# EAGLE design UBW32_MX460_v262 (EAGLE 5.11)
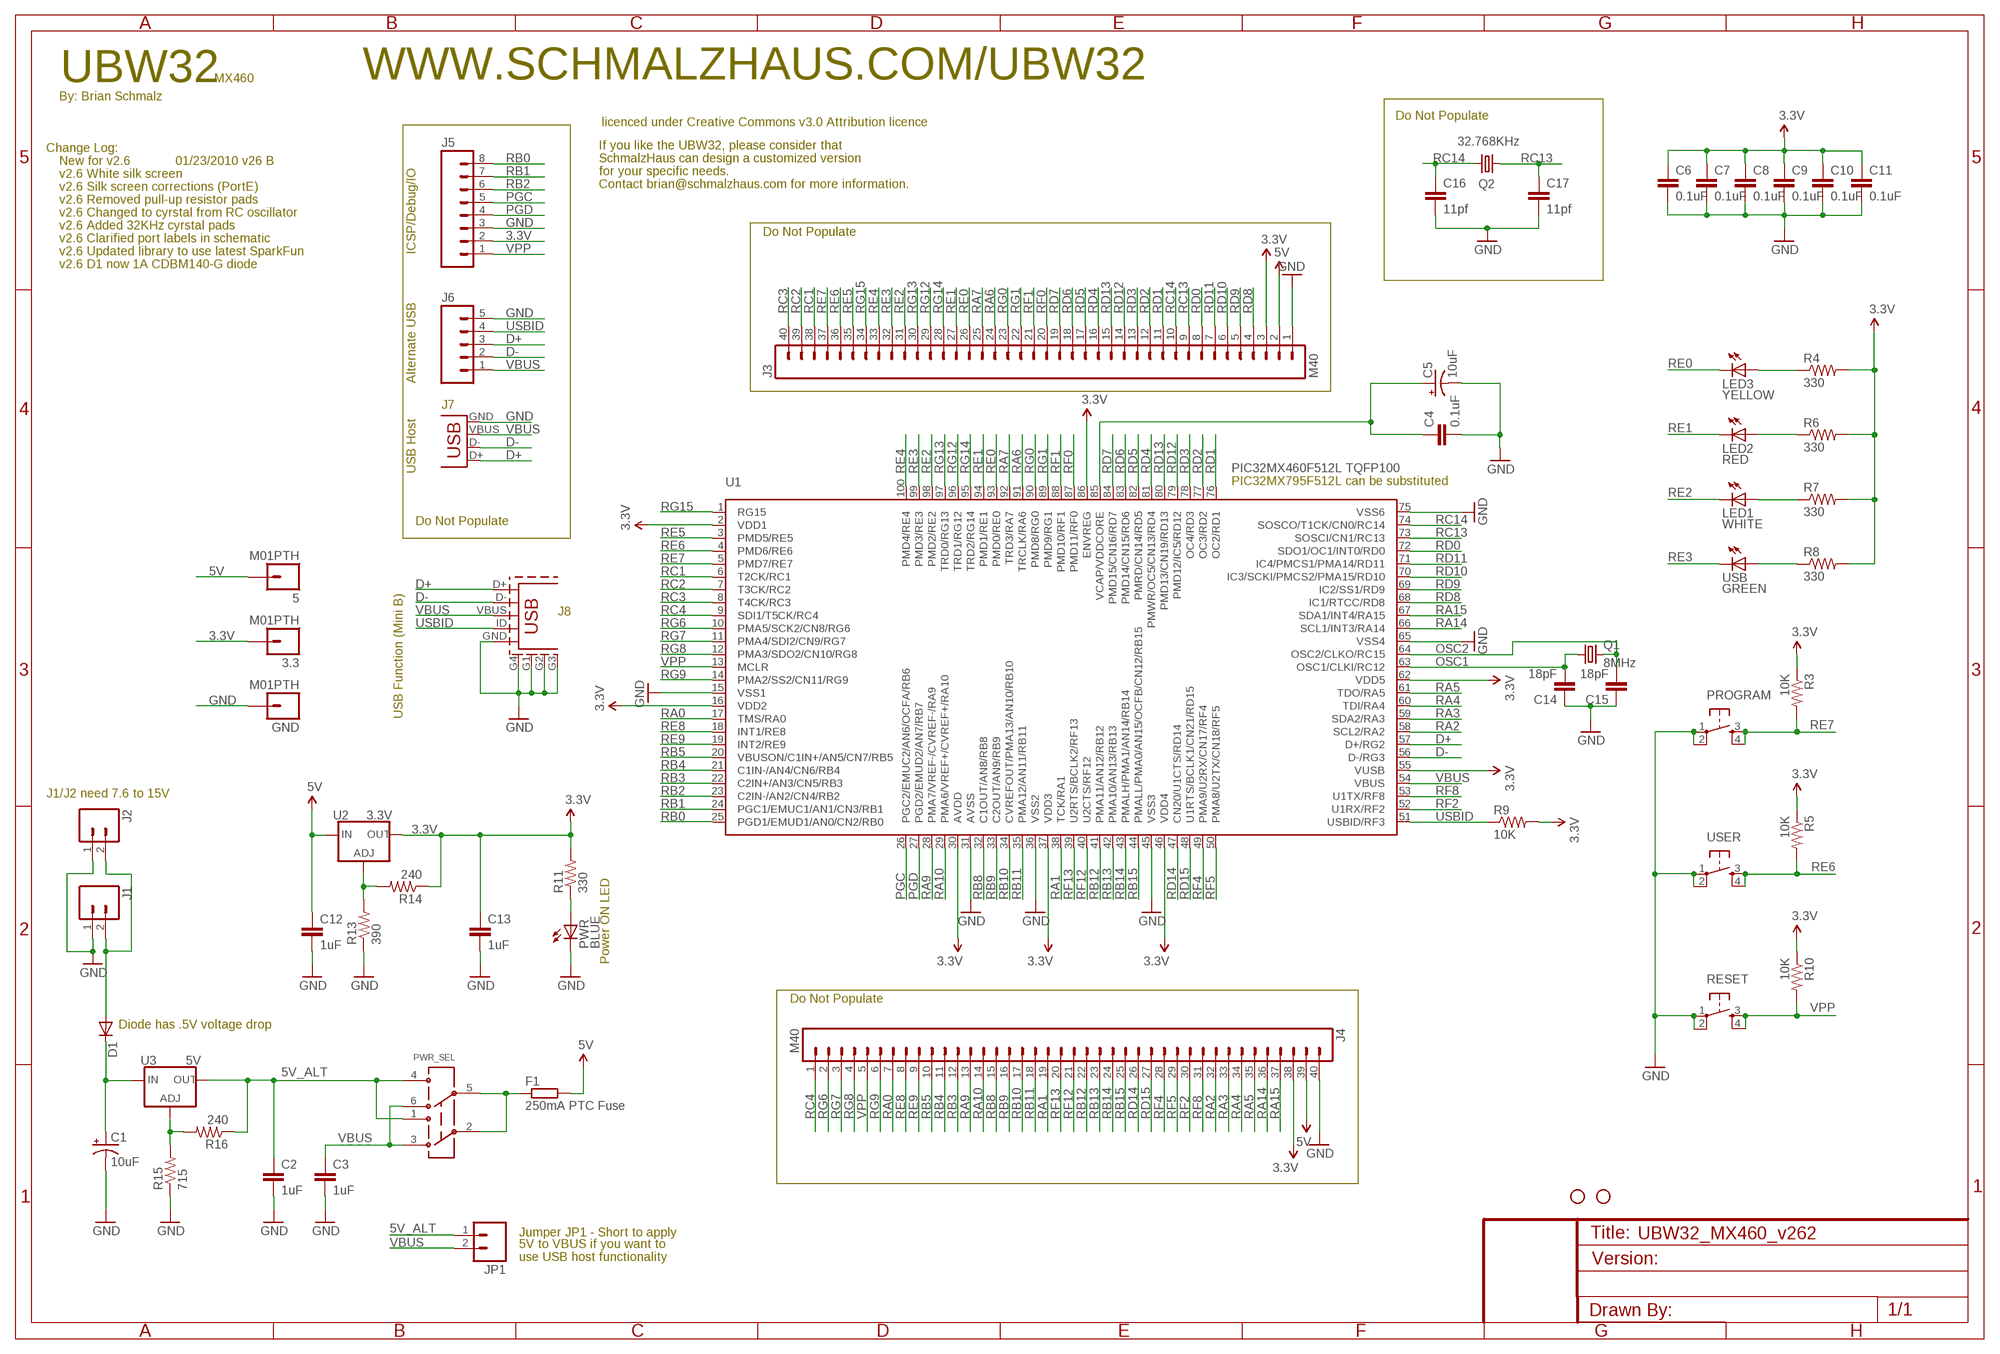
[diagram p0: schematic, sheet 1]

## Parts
3.3  M01PTH  [1X01]
5  M01PTH  [1X01]
C1  10uF  CAP_POL3528  [EIA3528]
C2  1uF  CAP0402-CAP  [0402-CAP]
C3  1uF  CAP0402-CAP  [0402-CAP]
C4  0.1uF  CAP0402-CAP  [0402-CAP]
C5  10uF  CAP_POL3528  [EIA3528]
C6  0.1uF  CAP0402-CAP  [0402-CAP]
C7  0.1uF  CAP0402-CAP  [0402-CAP]
C8  0.1uF  CAP0402-CAP  [0402-CAP]
C9  0.1uF  CAP0402-CAP  [0402-CAP]
C10  0.1uF  CAP0402  [C0402]
C11  0.1uF  CAP0402-CAP  [0402-CAP]
C12  1uF  CAP0402  [C0402]
C13  1uF  CAP0402  [C0402]
C14  18pF  CAP0402-CAP  [0402-CAP]
C15  18pF  CAP0402-CAP  [0402-CAP]
C16  11pf  CAP0402-CAP  [0402-CAP]
C17  11pf  CAP0402-CAP  [0402-CAP]
D1  DIODESMA  [SMA-DIODE]
F1  250mA PTC Fuse  R-EU_R1206  [R1206]
GND  M01PTH  [1X01]
J1  M02PTH  [1X02]
J2  M02-JST-2MM-SMT  [S2B-PH]
J3  M40  [1X40]
J4  M40  [1X40]
J5  M08  [1X08]
J6  M05PTH  [1X05]
J7  USB-A-S  [USB-A-S]
J8  USB_5PIN  [USB-MINIB]
JP1  M02PTH  [1X02]
LED1  WHITE  LED0603  [LED-0603]
LED2  RED  LED0603  [LED-0603]
LED3  YELLOW  LED0603  [LED-0603]
PROGRAM  TAC_SWITCHSND  [TACTILE_SWITCH_SMD]
PWR  BLUE  LED0603  [LED-0603]
PWR_SEL  AYZ0202  [AYZ0202]
Q1  8MHz  CRYSTAL5X3  [CRYSTAL-SMD-5X3]
Q2  32.768KHz  CRYSTAL32-SMD  [CRYSTAL-32KHZ-SMD]
R3  10K  RESISTOR0402-RES  [0402-RES]
R4  330  RESISTOR0402-RES  [0402-RES]
R5  10K  RESISTOR0402-RES  [0402-RES]
R6  330  RESISTOR0402-RES  [0402-RES]
R7  330  RESISTOR0402-RES  [0402-RES]
R8  330  RESISTOR0402-RES  [0402-RES]
R9  10K  RESISTOR0402-RES  [0402-RES]
R10  10K  RESISTOR0402-RES  [0402-RES]
R11  330  RESISTOR0402-RES  [0402-RES]
R13  390  RESISTOR0402-RES  [0402-RES]
R14  240  RESISTOR0402-RES  [0402-RES]
R15  715  RESISTOR0402-RES  [0402-RES]
R16  240  RESISTOR0402-RES  [0402-RES]
RESET  TAC_SWITCHSND  [TACTILE_SWITCH_SMD]
U1  PIC32MX460F512L TQFP100  PIC32MX4XXLTQFP100  [TQFP100]
U2  3.3V  V_REG_317SMD  [SOT223]
U3  5V  V_REG_317SMD  [SOT223]
U$6  STAND-OFF  [STAND-OFF]
U$7  STAND-OFF  [STAND-OFF]
USB  GREEN  LED0603  [LED-0603]
USER  TAC_SWITCHSND  [TACTILE_SWITCH_SMD]

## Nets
3.3V: 3.3.1 C6.1 C7.1 C8.1 C9.1 C10.1 C11.1 C13.1 J3.3 J4.38 J5.2 R3.1 R4.2 R5.1 R6.2 R7.2 R8.2 R9.2 R10.1 R11.2 R14.1 U1.2(VDD1) U1.16(VDD2) U1.30(AVDD) U1.37(VDD3) U1.46(VDD4) U1.55(VUSB) U1.62(VDD5) U1.86(ENVREG) U2.2(OUT)
5V: 5.1 C12.1 F1.2 J3.2 J4.39 U2.3(IN)
5V_ALT: C2.1 JP1.1 PWR_SEL.1 PWR_SEL.4 R16.1 U3.2(OUT)
D+: J6.3 J7.D+ J8.D+ U1.57(D+/RG2)
D-: J6.2 J7.D- J8.D- U1.56(D-/RG3)
GND: C1.C(-) C2.2 C3.2 C4.2 C5.C(-) C6.2 C7.2 C8.2 C9.2 C10.2 C11.2 C12.2 C13.2 C14.1 C15.1 C16.2 C17.2 GND.1 J1.1 J2.1 J3.1 J4.40 J5.3 J6.5 J7.GND J8.G1 J8.G2 J8.G3 J8.G4(SHIELD) J8.GND PROGRAM.1 PROGRAM.2 PWR.C R13.1 R15.1 RESET.1 RESET.2 U1.15(VSS1) U1.31(AVSS) U1.36(VSS2) U1.45(VSS3) U1.65(VSS4) U1.75(VSS6) USER.1 USER.2
N$1: D1.A J1.2 J2.2
N$2: F1.1 PWR_SEL.2 PWR_SEL.5
N$3: R13.2 R14.2 U2.1(ADJ)
N$4: R15.2 R16.2 U3.1(ADJ)
N$6: PWR.A R11.1
N$20: R8.1 USB.A
N$22: LED1.A R7.1
N$23: LED2.A R6.1
N$35: LED3.A R4.1
N$110: C4.1 C5.A(+) U1.85(VCAP/VDDCORE)
OSC1: C14.2 Q1.1 U1.63(OSC1/CLKI/RC12)
OSC2: C15.2 Q1.3 U1.64(OSC2/CLKO/RC15)
PGC: J5.5 U1.26(PGC2/EMUC2/AN6/OCFA/RB6)
PGD: J5.4 U1.27(PGD2/EMUD2/AN7/RB7)
RA0: J4.7 U1.17(TMS/RA0)
RA1: J4.19 U1.38(TCK/RA1)
RA2: J4.32 U1.58(SCL2/RA2)
RA3: J4.33 U1.59(SDA2/RA3)
RA4: J4.34 U1.60(TDI/RA4)
RA5: J4.35 U1.61(TDO/RA5)
RA6: J3.24 U1.91(TRCLK/RA6)
RA7: J3.25 U1.92(TRD3/RA7)
RA9: J4.13 U1.28(PMA7/VREF-/CVREF-/RA9)
RA10: J4.14 U1.29(PMA6/VREF+/CVREF+/RA10)
RA14: J4.36 U1.66(SCL1/INT3/RA14)
RA15: J4.37 U1.67(SDA1/INT4/RA15)
RB0: J5.8 U1.25(PGD1/EMUD1/AN0/CN2/RB0)
RB1: J5.7 U1.24(PGC1/EMUC1/AN1/CN3/RB1)
RB2: J5.6 U1.23(C2IN-/AN2/CN4/RB2)
RB3: J4.12 U1.22(C2IN+/AN3/CN5/RB3)
RB4: J4.11 U1.21(C1IN-/AN4/CN6/RB4)
RB5: J4.10 U1.20(VBUSON/C1IN+/AN5/CN7/RB5)
RB8: J4.15 U1.32(C1OUT/AN8/RB8)
RB9: J4.16 U1.33(C2OUT/AN9/RB9)
RB10: J4.17 U1.34(CVREFOUT/PMA13/AN10/RB10)
RB11: J4.18 U1.35(PMA12/AN11/RB11)
RB12: J4.22 U1.41(PMA11/AN12/RB12)
RB13: J4.23 U1.42(PMA10/AN13/RB13)
RB14: J4.24 U1.43(PMALH/PMA1/AN14/RB14)
RB15: J4.25 U1.44(PMALL/PMA0/AN15/OCFB/CN12/RB15)
RC1: J3.38 U1.6(T2CK/RC1)
RC2: J3.39 U1.7(T3CK/RC2)
RC3: J3.40 U1.8(T4CK/RC3)
RC4: J4.1 U1.9(SDI1/T5CK/RC4)
RC13: C17.1 J3.9 Q2.X1 U1.73(SOSCI/CN1/RC13)
RC14: C16.1 J3.10 Q2.X2 U1.74(SOSCO/T1CK/CN0/RC14)
RD0: J3.8 U1.72(SDO1/OC1/INT0/RD0)
RD1: J3.11 U1.76(OC2/RD1)
RD2: J3.12 U1.77(OC3/RD2)
RD3: J3.13 U1.78(OC4/RD3)
RD4: J3.16 U1.81(PMWR/OC5/CN13/RD4)
RD5: J3.17 U1.82(PMRD/CN14/RD5)
RD6: J3.18 U1.83(PMD14/CN15/RD6)
RD7: J3.19 U1.84(PMD15/CN16/RD7)
RD8: J3.4 U1.68(IC1/RTCC/RD8)
RD9: J3.5 U1.69(IC2/SS1/RD9)
RD10: J3.6 U1.70(IC3/SCKI/PMCS2/PMA15/RD10)
RD11: J3.7 U1.71(IC4/PMCS1/PMA14/RD11)
RD12: J3.14 U1.79(PMD12/IC5/RD12)
RD13: J3.15 U1.80(PMD13/CN19/RD13)
RD14: J4.26 U1.47(CN20/U1CTS/RD14)
RD15: J4.27 U1.48(U1RTS/BCLK1/CN21/RD15)
RE0: J3.26 LED3.C U1.93(PMD0/RE0)
RE1: J3.27 LED2.C U1.94(PMD1/RE1)
RE2: J3.31 LED1.C U1.98(PMD2/RE2)
RE3: J3.32 U1.99(PMD3/RE3) USB.C
RE4: J3.33 U1.100(PMD4/RE4)
RE5: J3.35 U1.3(PMD5/RE5)
RE6: J3.36 R5.2 U1.4(PMD6/RE6) USER.3 USER.4
RE7: J3.37 PROGRAM.3 PROGRAM.4 R3.2 U1.5(PMD7/RE7)
RE8: J4.8 U1.18(INT1/RE8)
RE9: J4.9 U1.19(INT2/RE9)
RF0: J3.20 U1.87(PMD11/RF0)
RF1: J3.21 U1.88(PMD10/RF1)
RF2: J4.30 U1.52(U1RX/RF2)
RF4: J4.28 U1.49(PMA9/U2RX/CN17/RF4)
RF5: J4.29 U1.50(PMA8/U2TX/CN18/RF5)
RF8: J4.31 U1.53(U1TX/RF8)
RF12: J4.21 U1.40(U2CTS/RF12)
RF13: J4.20 U1.39(U2RTS/BCLK2/RF13)
RG0: J3.23 U1.90(PMD8/RG0)
RG1: J3.22 U1.89(PMD9/RG1)
RG6: J4.2 U1.10(PMA5/SCK2/CN8/RG6)
RG7: J4.3 U1.11(PMA4/SDI2/CN9/RG7)
RG8: J4.4 U1.12(PMA3/SDO2/CN10/RG8)
RG9: J4.6 U1.14(PMA2/SS2/CN11/RG9)
RG12: J3.29 U1.96(TRD1/RG12)
RG13: J3.30 U1.97(TRD0/RG13)
RG14: J3.28 U1.95(TRD2/RG14)
RG15: J3.34 U1.1(RG15)
USBID: J6.4 J8.ID(USB_ID) R9.1 U1.51(USBID/RF3)
VBUS: C3.1 J6.1 J7.VBUS J8.VBUS JP1.2 PWR_SEL.3 PWR_SEL.6 U1.54(VBUS)
VIN_RAW: C1.A(+) D1.C U3.3(IN)
VPP: J4.5 J5.1 R10.2 RESET.3 RESET.4 U1.13(MCLR)

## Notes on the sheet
- UBW32 | MX460 | WWW.SCHMALZHAUS.COM/UBW32
- By: Brian Schmalz
- Do Not Populate
- licenced under Creative Commons v3.0 Attribution licence
- Change Log: | If you like the UBW32, please consider that
- New for v2.6 | 01/23/2010 v26 B | SchmalzHaus can design a customized version
- v2.6 White silk screen | for your specific needs.
- v2.6 Silk screen corrections (PortE) | Contact brian@schmalzhaus.com for more information.
- v2.6 Removed pull-up resistor pads
- v2.6 Changed to cyrstal from RC oscillator
- v2.6 Added 32KHz cyrstal pads
- Do Not Populate
- v2.6 Clarified port labels in schematic
- v2.6 Updated library to use latest SparkFun | ICSP/Debug/IO
- v2.6 D1 now 1A CDBM140-G diode
- Alternate USB
- J7
- USB Host
- PIC32MX795F512L can be substituted
- Do Not Populate
- J8
- USB Function (Mini B)
- J1/J2 need 7.6 to 15V
- Power ON LED
- Do Not Populate
- Diode has .5V voltage drop
- Jumper JP1 - Short to apply
- 5V to VBUS if you want to
- use USB host functionality

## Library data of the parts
3.3 5 GND = SparkFun-12-01-09:M01: Header 1
C1 C5 = SparkFun02-20-08:CAP_POL: Capacitor Polarized
C2-C4 C6-C9 C11 C14-C17 = SparkFun:CAP: Capacitor
C10 C12 C13 = SparkFun02-20-08:CAP: Capacitor
D1 = SparkFun-12-01-09:DIODE: Diode
F1 = resistor:R-EU_: RESISTOR, European symbol
J1 JP1 = SparkFun-12-01-09:M02: Header 2
J2 = SparkFun:M02: Header 2
J3 J4 = SchmalzHaus:M40
J5 = SchmalzHaus:M08: Header 8 Standard 8-pin 0.1" header. Use with straight break away headers (SKU : PRT-00116), right angle break away headers (PRT-00553), swiss pins (PRT-00743), machine pins (PRT-00117), and female headers (PRT-00115).
J6 = SparkFun-12-01-09:M05: Header 5 Standard 5-pin 0.1" header. Use with straight break away headers (SKU : PRT-00116), right angle break away headers (PRT-00553), swiss pins (PRT-00743), machine pins (PRT-00117), and female headers (PRT-00115). Molex polarized connector foot print use with SKU : PRT-08230 with associated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
J7 = SparkFun02-20-08:USB: USB Connectors USB-B-PTH is fully proven SKU : PRT-00139 USB-miniB is fully proven SKU : PRT-00587 USB-A-PCB is untested. USB-A-H is throughly reviewed, but untested. Spark Fun Electronics SKU : PRT-00437 USB-B-SMT is throughly reviewed, but untested. Needs silkscreen touching up. USB-A-S has not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
J8 = SparkFun02-20-08:USB_5PIN
LED1-LED3 PWR USB = SparkFun:LED: LEDs
PROGRAM RESET USER = SparkFun02-20-08:TAC_SWITCH: Momentary Switch Button commonly used for reset or general input. Spark Fun Electronics SKU : COM-00097
PWR_SEL = SparkFun02-20-08:AYZ0202: SPDT Slide Switch Simple SMD single-pull double-throw slide switch. Good for less than 350mA power switch, switching UARTs between devices, etc. Spark Fun Electronics SKU : COM-00597
Q1 = SparkFun11_03_09:CRYSTAL: Crystals
Q2 = SchmalzHaus:CRYSTAL: Crystals
R3-R11 R13-R16 = SparkFun:RESISTOR: Resistor
U1 = SchmalzHaus:PIC32MX4XXL
U2 U3 = SparkFun:V_REG_317: Voltage Regulator Standard LM317 adjustable voltage regulator. AOI (Adjust Output Input). Google 'LM317 Calculator' for easy to use app to get the two resistor values needed. 240/720 for 5V output. 240/390 for 3.3V output. Spark Fun Electronics SKU : COM-00527
U$6 U$7 = SparkFun02-20-08:STAND-OFF: Stand Off

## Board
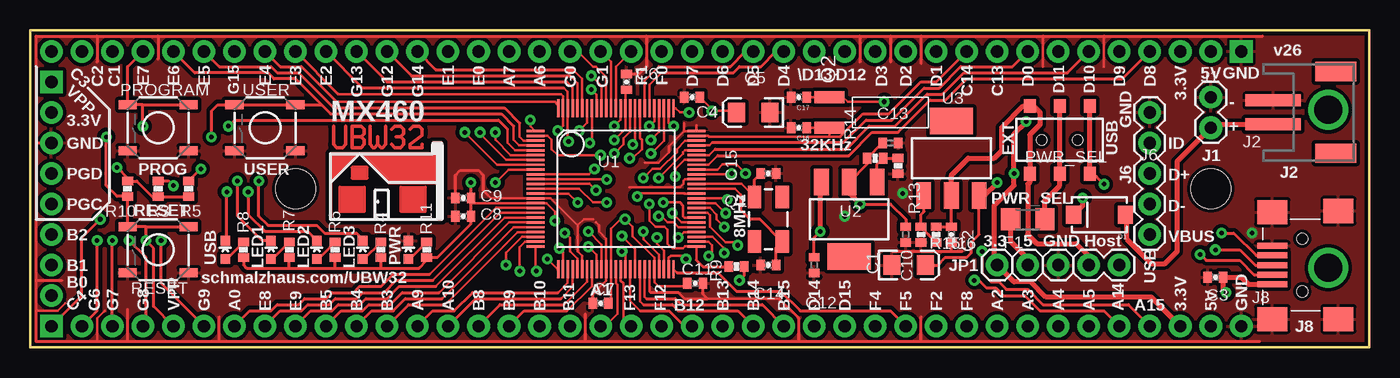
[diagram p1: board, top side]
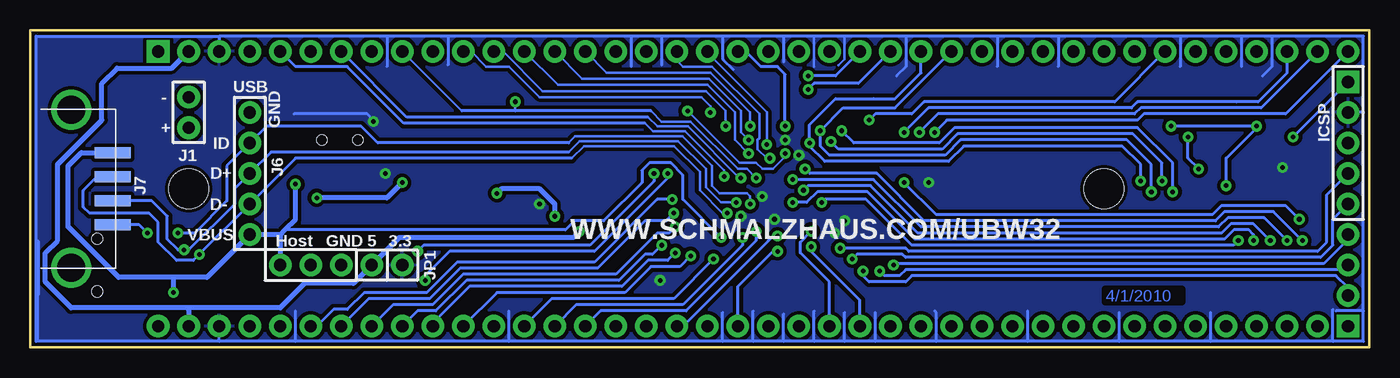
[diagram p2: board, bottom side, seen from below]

Size 111.51 x 26.42 mm. Coordinates in mm from the lower left corner, seen from the top.
Outline: 0,26.42 111.51,26.42 111.51,0 0,0 0,26.42
Copper layers (1*16): Top 0.035mm / dielectric 1.5mm / Bottom 0.035mm
Design rules "SparkFun *": minimum track width 8mil, minimum drill 15mil, track to track 8mil, track to pad 8mil, pad to pad 8mil, via to via 8mil, smd to smd 8mil, copper to edge 8mil, drill to drill 8mil, minimum pad ring 12mil, minimum via ring 10mil, stop-mask expansion 4mil, vias tented up to drill 20mil, thermal gap 10mil

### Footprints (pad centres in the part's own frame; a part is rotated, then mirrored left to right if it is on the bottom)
1X01 = drill 1.016 pad 1.88 round: 1 0,0
EIA3216 = smd 1.4 x 1.6: A 1.4,0; C -1.4,0
0402-CAP = smd 0.7 x 0.9: 1 -0.65,0; 2 0.65,0
C0402 = smd 0.7 x 0.9: 1 -0.65,0; 2 0.65,0
SMA-DIODE = smd 1.27 x 1.47: A -2.15,0; C 2.15,0
R1206 = smd 1.6 x 1.803: 1 -1.422,0; 2 1.422,0
1X02 = drill 1.016 pad 1.88 round: 1 0,0; 2 2.54,0
S2B-PH = smd 1 x 4.6: 1 -1,-3.7; 2 1,-3.7 | smd 1.6 x 3.4: NC1 -3.4,1.5; NC2 3.4,1.5
1X40 = drill 1.016 pad 1.88 square: 1 -49.53,0 | drill 1.016 pad 1.88 round: 2 -46.99,0; 3 -44.45,0; 4 -41.91,0; 5 -39.37,0; 6 -36.83,0; 7 -34.29,0; 8 -31.75,0; 9 -29.21,0; 10 -26.67,0; 11 -24.13,0; 12 -21.59,0; 13 -19.05,0; 14 -16.51,0; 15 -13.97,0; 16 -11.43,0; 17 -8.89,0; 18 -6.35,0; 19 -3.81,0; 20 -1.27,0; 21 1.27,0; 22 3.81,0; 23 6.35,0; 24 8.89,0; 25 11.43,0; 26 13.97,0; 27 16.51,0; 28 19.05,0; 29 21.59,0; 30 24.13,0; 31 26.67,0; 32 29.21,0; 33 31.75,0; 34 34.29,0; 35 36.83,0; 36 39.37,0; 37 41.91,0; 38 44.45,0; 39 46.99,0; 40 49.53,0
1X08 = drill 1.016 pad 1.88 square: 1 0,0 | drill 1.016 pad 1.88 round: 2 2.54,0; 3 5.08,0; 4 7.62,0; 5 10.16,0; 6 12.7,0; 7 15.24,0; 8 17.78,0
1X05 = drill 1.016 pad 1.88 round: 1 0,0; 2 2.54,0; 3 5.08,0; 4 7.62,0; 5 10.16,0
USB-A-S = smd 3 x 0.9: D+ 3.45,-1; D- 3.45,1; GND 3.45,-3; VBUS 3.45,3 | drill 2.311 round: P$5 0,-6.566; P$6 0,6.566
USB-MINIB = smd 2.5 x 0.5: D+ 2.5,0; D- 2.5,0.8; GND 2.5,-1.6; ID 2.5,-0.8; VBUS 2.5,1.6 | smd 2.5 x 2: G1 -3,4.5; G2 2.5,4.5; G3 -3,-4.5; G4 2.5,-4.4 | hole 0.9: 0,2.2; 0,-2.2
LED-0603 = smd 0.8 x 0.8: A 0,-0.75; C 0,0.75
TACTILE_SWITCH_SMD = smd 1.524 x 0.762: 1 -2.54,1.905; 2 2.54,1.905; 3 -2.54,-1.905; 4 2.54,-1.905
AYZ0202 = smd 1 x 1.15: 1 -2.5,2.825; 2 0,2.825; 3 2.5,2.825; 4 -2.5,-2.825; 5 0,-2.825; 6 2.5,-2.825 | hole 0.85: 1.5,0; -1.5,0
CRYSTAL-SMD-5X3 = smd 1.9 x 1.1: 1 -1.85,-1.15; 2 1.85,-1.15; 3 1.85,1.15; 4 -1.85,1.15
CRYSTAL-32KHZ-SMD = smd 1 x 2.5: X1 -1.27,0; X2 1.27,0
0402-RES = smd 0.7 x 0.9: 1 -0.65,0; 2 0.65,0
TQFP100 = smd 0.2 x 1.5: 1 -4.8,-6.7; 2 -4.4,-6.7; 3 -4,-6.7; 4 -3.6,-6.7; 5 -3.2,-6.7; 6 -2.8,-6.7; 7 -2.4,-6.7; 8 -2,-6.7; 9 -1.6,-6.7; 10 -1.2,-6.7; 11 -0.8,-6.7; 12 -0.4,-6.7; 13 0,-6.7; 14 0.4,-6.7; 15 0.8,-6.7; 16 1.2,-6.7; 17 1.6,-6.7; 18 2,-6.7; 19 2.4,-6.7; 20 2.8,-6.7; 21 3.2,-6.7; 22 3.6,-6.7; 23 4,-6.7; 24 4.4,-6.7; 25 4.8,-6.7; 51 4.8,6.7; 52 4.4,6.7; 53 4,6.7; 54 3.6,6.7; 55 3.2,6.7; 56 2.8,6.7; 57 2.4,6.7; 58 2,6.7; 59 1.6,6.7; 60 1.2,6.7; 61 0.8,6.7; 62 0.4,6.7; 63 0,6.7; 64 -0.4,6.7; 65 -0.8,6.7; 66 -1.2,6.7; 67 -1.6,6.7; 68 -2,6.7; 69 -2.4,6.7; 70 -2.8,6.7; 71 -3.2,6.7; 72 -3.6,6.7; 73 -4,6.7; 74 -4.4,6.7; 75 -4.8,6.7 | smd 1.5 x 0.2: 26 6.7,-4.8; 27 6.7,-4.4; 28 6.7,-4; 29 6.7,-3.6; 30 6.7,-3.2; 31 6.7,-2.8; 32 6.7,-2.4; 33 6.7,-2; 34 6.7,-1.6; 35 6.7,-1.2; 36 6.7,-0.8; 37 6.7,-0.4; 38 6.7,0; 39 6.7,0.4; 40 6.7,0.8; 41 6.7,1.2; 42 6.7,1.6; 43 6.7,2; 44 6.7,2.4; 45 6.7,2.8; 46 6.7,3.2; 47 6.7,3.6; 48 6.7,4; 49 6.7,4.4; 50 6.7,4.8; 76 -6.7,4.8; 77 -6.7,4.4; 78 -6.7,4; 79 -6.7,3.6; 80 -6.7,3.2; 81 -6.7,2.8; 82 -6.7,2.4; 83 -6.7,2; 84 -6.7,1.6; 85 -6.7,1.2; 86 -6.7,0.8; 87 -6.7,0.4; 88 -6.7,0; 89 -6.7,-0.4; 90 -6.7,-0.8; 91 -6.7,-1.2; 92 -6.7,-1.6; 93 -6.7,-2; 94 -6.7,-2.4; 95 -6.7,-2.8; 96 -6.7,-3.2; 97 -6.7,-3.6; 98 -6.7,-4; 99 -6.7,-4.4; 100 -6.7,-4.8
SOT223 = smd 1.219 x 2.235: 1 -2.311,-3.099; 2 0,-3.099; 3 2.311,-3.099 | smd 3.6 x 2.2: 4 0,3.099
STAND-OFF = hole 3.302: 0,0

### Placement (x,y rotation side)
3.3  80.52,6.86 0 top
5  83.06,6.86 0 top
C1  10uF  [EIA3216]  73.15,6.86 0 top
C2  76.71,9.4 270 top
C3  98.68,5.84 180 top
C4  55.12,20.83 180 top
C5  10uF  [EIA3216]  60.2,19.56 180 top
C6  49.66,22.1 90 top
C7  47.5,3.68 180 top
C8  36.07,10.92 180 top
C9  36.07,12.45 180 top
C10  72.9,9.4 270 top
C11  55.37,5.33 0 top
C12  65.28,6.86 270 top
C13  71.63,17.02 0 top
C14  61.47,6.86 0 top
C15  61.47,14.48 180 top
C16  64.01,18.29 180 top
C17  64.01,20.83 180 top
D1  89.03,11.05 180 top
F1  83.06,10.67 180 top
GND  85.6,6.86 0 top
J1  98.3,20.83 270 top
J2  107.19,19.56 270 top
J3  51.31,24.64 180 top
J4  51.31,1.78 0 top
J5  1.78,22.1 270 top
J6  93.22,9.4 90 top
J7  108.08,13.21 0 bottom
J8  105.92,6.86 180 top
JP1  88.14,6.86 0 top
LED1  20.07,8.13 0 top
LED2  23.88,8.13 0 top
LED3  27.69,8.13 0 top
PROGRAM  10.67,18.29 180 top
PWR  31.5,8.13 0 top
PWR_SEL  85.72,17.27 0 top
Q1  61.47,10.67 90 top
Q2  66.55,19.56 270 top
R3  10.67,13.21 90 top
R4  29.21,8.13 270 top
R5  13.21,13.21 90 top
R6  25.4,8.13 270 top
R7  21.59,8.13 270 top
R8  17.78,8.13 270 top
R9  58.8,6.73 0 top
R10  8.13,13.21 270 top
R11  33.02,8.13 270 top
R13  72.26,15.11 90 top
R14  70.36,15.75 0 top
R15  74.17,9.4 90 top
R16  75.44,9.4 270 top
RESET  10.67,8.13 180 top
U1  48.77,13.21 270 top
U2  68.2,10.67 180 top
U3  76.71,15.75 0 top
U$3  [UBW32]  29.59,17.91 0 top
U$5  [SCHMALZHAUS]  28.83,13.21 0 top
U$6  98.3,13.21 0 top
U$7  22.1,13.21 0 top
USB  16.26,8.13 0 top
USER  19.56,18.29 180 top

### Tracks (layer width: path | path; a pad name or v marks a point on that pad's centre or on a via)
3.3V  (via drill 0.38)
  Top 0.203: v48.64,17.27 49.57,18.2 U1.86 49.57,21.36 arc-90 C6.1 | v43.69,10.54 43.69,11.3 42.98,12.01 U1.16 36.77,12.01 | v44.51,9.52 44.58,9.52 44.96,9.14 44.96,8 45.57,7.39 U1.30 | U1.2 43.1,17.61 43.43,17.27 43.43,16.51 43.94,16 v47.5,16 | 48.37,3.92 U1.37 48.37,9.89 49.15,10.67 v49.53,10.67 50.16,10.03 50.16,9.27 51.97,7.47 U1.46 51.97,5.44 52.32,5.08 54.48,5.08 54.74,5.33 C11.1 | U1.62 54.5,12.81 54.48,12.83 50.8,12.83 v50.55,12.57 | U1.55 54,10.01 53.59,10.41 53.09,10.41 52.58,10.92 v52.32,10.92
  Top 0.254: v36.7,13.72 36.72,13.7 C9.1 36.7,12.45 36.7,11.94 | 36.7,10.92 C8.1 | 36.7,10.92 36.7,11.94 | 36.7,11.94 36.77,12.01 | 36.7,10.92 36.7,10.29 33.91,7.49 33.02,7.49 R11.2 33.02,7.24 32.38,6.6 29.21,6.6 | 21.59,6.6 25.4,6.6 | 25.4,6.6 29.21,6.6 | 29.21,6.6 R4.2 | 25.4,6.6 R6.2 | 21.59,6.6 R7.2 | R8.2 17.78,6.87 18.05,6.6 21.59,6.6 | C7.1 48.13,3.68 48.37,3.92 | R5.1 R3.1 10.18,12.56 8.89,13.84 8.14,13.84 R10.1 8.13,14.1 v7.24,14.99 | C13.1 R14.1 69.71,15.28 U2.2 | 72.88,10.03 C10.1 72.9,10.67 71.63,11.94 v69.09,11.94 | R9.2 59.45,5.98 v59.05,5.59
  Top 0.406: J4.38 93.34,4.19 84.58,4.19 83.31,5.46 81.91,5.46 3.3.1 80.26,7.11 80.26,11.81 81.91,13.46 v81.91,14.48 81.91,17.78 v82.93,18.8 | v69.09,11.94 68.2,12.83 U2.2
  Bottom 0.203: 43.69,25.91 43.69,24 44.2,23.49 | 46.23,25.91 46.23,23.37
  Bottom 0.254: 89.53,19.43 83.44,19.43 82.93,18.92 v82.93,18.8 | 0.51,3.05 0.51,0.51 3.05,0.51 | 0.51,3.05 0.51,19.56 | 0.51,19.56 0.51,25.91 8.13,25.91 | 8.13,25.91 10.67,25.91 | 10.67,25.91 15.75,25.91 | 15.75,25.91 25.91,25.91 | 25.91,25.91 30.99,25.91 | 30.99,25.91 38.61,25.91 | 38.61,25.91 43.69,25.91 46.23,25.91 48.77,25.91 | 48.77,25.91 53.85,25.91 | 81.79,25.91 95.76,25.91 | 76.71,25.91 81.79,25.91 | 61.47,25.91 76.71,25.91 | 58.93,25.91 61.47,25.91 | 53.85,25.91 58.93,25.91 | 95.76,25.91 111,25.91 111,0.51 | 3.05,0.51 13.21,0.51 | 13.21,0.51 20.83,0.51 | 20.83,0.51 28.45,0.51 | 28.45,0.51 36.07,0.51 | 36.07,0.51 41.15,0.51 | 41.15,0.51 43.69,0.51 | 43.69,0.51 46.23,0.51 | 46.23,0.51 48.77,0.51 | 48.77,0.51 51.31,0.51 | 51.31,0.51 53.85,0.51 | 53.85,0.51 71.63,0.51 | 71.63,0.51 89.41,0.51 | 89.41,0.51 95.76,0.51 | 95.76,0.51 111,0.51 | 0.51,19.56 2.03,19.56 | 0.51,3.05 2.79,3.05 | 3.05,0.51 3.05,3.17 | 41.15,0.51 41.15,2.92 | 48.77,0.51 48.77,2.79 | 53.85,25.91 53.85,24 52.96,23.11 | 95.76,25.91 95.76,24.13 | 95.76,0.51 J4.38 | 89.41,0.51 89.41,3.05 | 25.91,25.91 25.91,23.37 | 30.99,25.91 30.99,23.37 | 48.77,25.91 48.77,23.75 | 38.61,25.91 38.61,23.37 39.37,22.61 | 15.75,25.91 15.75,23.37 | 10.67,25.91 10.67,23.37 | 8.13,25.91 8.13,23.37 8.89,22.61 | 13.21,0.51 13.21,2.92 | 20.83,0.51 20.83,2.92 | 28.45,0.51 28.45,3.05 | 36.07,0.51 36.07,2.92 36.2,3.05 | 43.69,0.51 43.69,2.92 | 53.85,0.51 53.85,2.92 | 51.31,0.51 51.31,3.05 | 46.23,0.51 46.23,3.05 | 71.63,0.51 71.63,3.05 | 76.71,25.91 76.71,23.49 | 81.79,25.91 81.79,23.37 | 58.93,25.91 58.93,23.49 | 61.47,25.91 61.47,23.37 | 110.87,4.45 110.87,0.64 111,0.51
  Bottom 0.406: 110.87,4.45 110.87,8.76
  pour Bottom (isolate 0.305): 0.51,0.51 0.51,25.91 111,25.91 111,0.51
5V  (via drill 0.38)
  Top 0.254: C12.1 65.28,9.14 v65.79,9.65
  Top 0.406: F1.2 81.64,8.79 83.06,7.37 5.1 | U2.3 65.79,13.66 v65.79,9.65
  Bottom 0.254: 98.42,3.3 98.3,3.17
  Bottom 0.406: v65.79,9.65 66.29,9.14 80.77,9.14 5.1 84.58,5.33 88.65,5.33 90.68,3.3 98.42,3.3 108.08,3.3 110.24,5.46 110.24,7.87 109.22,8.89 109.22,15.24 105.54,18.92 105.54,21.97 104.27,23.24 99.69,23.24 J3.2 | 98.3,3.17 J4.39
5V_ALT
  Top 0.254: 76.71,12.57 U3.2 C2.1 R16.1
  Top 0.406: JP1.1 88.14,7.62 87.12,8.64 83.82,8.64 83.06,9.4 83.06,13.59 83.22,13.76 PWR_SEL.4 83.22,17.69 84.07,18.54 84.07,19.56 83.53,20.1 PWR_SEL.1 82.71,20.1 80.9,18.29 80.9,16.38 80.26,15.75 78.1,15.75 76.71,14.35 U3.2
D+  (via drill 0.38)
  Top 0.203: U1.57 54.47,10.81 54.36,10.92 54.36,11.81 54.1,12.07 v52.71,12.07
  Top 0.254: J8.D+ 101.98,6.86 100.71,8.13 v98.68,8.13
  Bottom 0.203: 66.67,16.26 65.76,17.17 57.56,17.17 55.25,14.86 55.25,13.34 53.98,12.07 v52.71,12.07
  Bottom 0.254: 66.67,16.26 91.44,16.26 J6.3 94.49,13.21 94.49,11.94 98.3,8.13 v98.68,8.13 99.19,8.13 100.08,9.02 100.08,10.92 101.36,12.21 J7.D+
D-  (via drill 0.38)
  Top 0.203: U1.56 54.23,10.41 v53.47,11.18
  Top 0.254: v97.41,7.75 97.92,7.24 100.71,7.24 101.89,6.06 J8.D-
  Bottom 0.203: 66.42,15.75 65.41,16.76 61.47,16.76 57.91,16.76 55.75,14.61 55.75,13.08 53.85,11.18 v53.47,11.18
  Bottom 0.254: 66.42,15.75 89.41,15.75 J6.2 v97.41,7.75 97.92,7.24 99.31,7.24 100.84,8.76 100.84,10.41 101.6,11.18 106.55,11.18 107.06,11.68 107.06,13.08 105.93,14.21 J7.D-
GND  (via drill 0.38)
  Top 0.203: 38.1,12.7 38.39,12.41 U1.15 43.35,12.41 45.59,10.16 | 46.86,4.45 47.97,5.55 U1.36 47.97,9.05 47.37,9.65 47.37,10.16 47.12,10.41 | 54.46,18.01 53.21,16.76 53.21,16.26 52.32,15.37 51.18,15.37 | U1.31 45.97,7.63 45.59,8 45.59,10.16 | 45.59,10.16 46.1,10.67 46.86,10.67 | 55.47,18.51 U1.75 54.46,18.01 | U1.65 54.54,14.01 54.39,13.86 54.39,13.63 54.1,13.34 49.91,13.34 | 54.46,18.01 54.46,18.68 | 89.41,25.91 89.41,23.37 | 84.33,25.91 84.33,23.37 | 5.59,0.51 5.59,2.41 6.22,3.05 | 0.51,3.05 2.29,3.05 2.92,3.68 | U1.45 51.57,4.69 51.69,4.57 | 62.36,4.06 54.48,4.06
  Top 0.254: C9.2 35.42,14.34 35.81,14.73 37.34,14.73 37.72,14.35 37.72,13.08 38.1,12.7 | C7.2 46.86,3.68 46.86,4.45 | 51.69,4.57 53.98,4.57 54.48,4.06 56.39,4.06 56.02,4.43 C11.2 | C6.2 50.69,22.75 51.31,23.37 51.31,25.91 | 51.31,25.91 69.09,25.91 | 69.09,25.91 69.09,23.75 | 5.59,25.91 0.51,25.91 0.51,17.02 | 5.59,25.91 10.67,25.91 | 10.67,25.91 51.31,25.91 | 0.51,5.59 0.51,3.05 0.51,0.51 5.59,0.51 8.13,0.51 | 0.51,5.59 0.51,17.02 | 8.13,0.51 15.75,0.51 | 15.75,0.51 46.23,0.51 | 46.23,0.51 64.01,0.51 | 64.01,0.51 74.17,0.51 | 74.17,0.51 102.36,0.51 | 69.09,25.91 71.63,25.91 | 71.63,25.91 74.17,25.91 | 74.17,25.91 84.33,25.91 89.41,25.91 102.62,25.91 | 46.23,0.51 46.23,2.79 | 64.01,0.51 64.01,2.41 62.36,4.06 | 5.59,25.91 5.59,23.75 | 0.51,17.02 1.91,17.02 | 0.51,5.59 2.67,5.59 | 8.13,0.51 8.13,3.17 | 15.75,0.51 15.75,2.54 | 74.17,0.51 74.17,2.54 | 10.67,25.91 10.67,24 | 71.63,25.91 71.63,23.75 | 74.17,25.91 74.17,23.62 | 71.75,8 76.71,8 | 76.71,8 77.6,8 | 76.71,8 C2.2
  Bottom 0.254: v101.73,9.52 102.41,10.21 J7.GND
  Bottom 0.406: v67.82,10.92 67.82,11.94 69.09,13.21 72.26,13.21 v72.64,12.83
  pour Top (isolate 0.305, rank 2): 0.51,25.91 0.51,0.51 111,0.51 111,25.91
N$1
  Top 0.406: J2.2 98.57,18.56 J1.2 95.5,15.49 95.5,8 94.49,6.99 93.34,6.99 91.31,9.02 91.31,10.91 D1.A
N$2
  Top 0.406: PWR_SEL.2 PWR_SEL.5 85.72,13.46 84.48,12.22 F1.1
N$3
  Top 0.254: R13.2 72.25,15.75 R14.2 70.51,15.25 U2.1
N$4
  Top 0.254: 74.4,12.47 U3.1 74.42,12.62 74.42,11.3 74.17,11.05 R15.2 74.17,10.03 74.8,9.4 74.8,9.38 R16.2
N$6
  Top 0.254: R11.1 33.02,8.76 31.63,7.38 PWR.A
N$20
  Top 0.254: USB.A 16.39,7.38 17.78,8.76 17.65,8.76 17.67,8.78 R8.1
N$22
  Top 0.254: R7.1 21.59,8.76 20.2,7.38 LED1.A
N$23
  Top 0.254: R6.1 25.4,8.76 24.02,7.38 LED2.A
N$35
  Top 0.254: R4.1 29.21,8.76 27.82,7.38 LED3.A
N$110  (via drill 0.38)
  Top 0.203: U1.85 49.97,17.96 49.4,17.4 49.4,16.89 v48.64,16.13 | C5.A 58.67,19.68 v56.77,19.68 56.77,19.83 C4.1
  Bottom 0.203: v48.64,16.13 48.64,15.88 49.66,14.86 50.55,14.86 51.05,15.37 52.45,15.37 v56.77,19.68
OSC1
  Top 0.203: U1.63 58.67,13.21 59.18,12.7
  Top 0.254: 59.18,12.7 59.18,11.43 59.94,10.67 60.77,10.67 Q1.1 62.12,8.32 C14.2
OSC2
  Top 0.203: U1.64 59.23,13.61 Q1.3
  Top 0.254: Q1.3 60.32,13.98 C15.2
PGC  (via drill 0.38)
  Top 0.203: U1.26 43.92,6.5 v43.05,7.37
  Bottom 0.254: J5.5 3.05,10.67 3.05,8.51 4.06,7.49 38.61,7.49 38.86,7.75 42.67,7.75 v43.05,7.37
PGD  (via drill 0.38)
  Top 0.203: U1.27 44.37,7.92 44.07,8.22 v44.07,8.25
  Bottom 0.254: v44.07,8.25 38.61,8.25 38.35,8 4.32,8 3.56,8.76 3.56,12.7 J5.4
RA0
  Top 0.203: U1.17 38.79,11.61 33.27,6.1
  Top 0.254: 33.27,6.1 30.23,6.1 29.21,5.08 27.43,5.08 26.92,4.57 25.15,4.57 24.64,4.06 22.86,4.06 22.35,3.56 20.57,3.56 20.07,3.05 18.29,3.05 J4.7
RA1
  Top 0.203: U1.38 48.77,5.33 48.9,5.21 48.9,2.79 47.88,1.78 J4.19
RA2  (via drill 0.38)
  Top 0.203: U1.58 56.39,11.21 56.61,10.98 56.61,10.07 57.91,8.76 58.67,8.76 v58.93,8.51
  Bottom 0.254: v58.93,8.51 59.69,7.75 60.33,7.75 62.48,5.59 75.18,5.59 77.72,3.05 79.25,3.05 J4.32
RA3  (via drill 0.38)
  Top 0.203: U1.59 56.59,11.61 57.15,11.05 57.15,10.67 v57.79,10.03
  Bottom 0.254: J4.33 81.28,3.56 77.98,3.56 75.44,6.1 62.74,6.1 59.31,9.52 58.29,9.52 v57.79,10.03
RA4  (via drill 0.38)
  Top 0.203: U1.60 57.08,12.01 v57.91,11.18
  Bottom 0.254: J4.34 83.31,4.06 78.23,4.06 75.69,6.6 64.26,6.6 60.33,10.54 58.55,10.54 v57.91,11.18
RA5  (via drill 0.38)
  Top 0.203: U1.61 57.95,12.41 v58.04,12.32
  Bottom 0.254: v58.04,12.32 59.31,12.32 64.52,7.11 75.95,7.11 78.49,4.57 83.69,4.57 85.09,3.17 86.23,3.17 87.63,1.78 J4.35
RA6  (via drill 0.38)
  Top 0.203: U1.91 47.57,21.77 v46.74,22.61
  Bottom 0.254: v46.74,22.61 44.45,22.61 J3.24
RA7  (via drill 0.38)
  Top 0.203: U1.92 47.17,21.03 v46.74,21.46
  Bottom 0.254: v46.74,21.46 46.23,21.97 42.55,21.97 J3.25
RA9
  Top 0.203: U1.28 44.77,5.4 43.94,4.57
  Top 0.254: 43.94,4.57 36.83,4.57 35.31,3.05 33.53,3.05 J4.13
RA10
  Top 0.203: U1.29 45.17,5.04 44.2,4.06
  Top 0.254: 44.2,4.06 37.08,4.06 J4.14
RA14  (via drill 0.38)
  Top 0.203: U1.66 58.35,14.41 v58.42,14.48
  Top 0.254: J4.36 89.41,3.05 84.07,3.05 82.8,4.32 81.03,4.32 80.39,4.95 79.63,4.95 78.99,5.59 v78.61,5.59
  Bottom 0.254: v58.42,14.48 58.42,14.1 64.52,8 76.58,8 78.61,5.97 v78.61,5.59
RA15  (via drill 0.38)
  Top 0.203: U1.67 57.23,14.81 57.66,15.24 58.8,15.24 v59.56,14.48
  Top 0.254: J4.37 91.44,3.56 84.33,3.56 83.06,4.83 81.28,4.83 80.64,5.46 80.01,5.46 79.25,6.22 v79.25,8
  Bottom 0.254: v59.56,14.48 59.56,13.84 64.9,8.51 78.74,8.51 v79.25,8
RB0  (via drill 0.38)
  Top 0.203: U1.25 42.07,6.45 v42.16,6.35
  Bottom 0.254: J5.8 1.78,4.95 2.79,5.97 38.1,5.97 38.61,5.46 41.66,5.46 42.16,5.97 v42.16,6.35
RB1  (via drill 0.38)
  Top 0.203: U1.24 41.22,8.81 40.77,8.36 v40.77,6.35
  Bottom 0.254: v40.77,6.35 40.39,5.97 39.12,5.97 38.61,6.48 2.16,6.48 J5.7
RB2  (via drill 0.38)
  Top 0.203: U1.23 40.96,9.21 39.62,7.87 v39.62,6.86
  Bottom 0.254: v39.62,6.86 39.5,6.99 3.81,6.99 1.78,9.02 J5.6
RB3
  Top 0.203: U1.22 40.6,9.61 34.54,3.56
  Top 0.254: 34.54,3.56 31.5,3.56 J4.12
RB4
  Top 0.203: U1.21 40.23,10.01 34.29,4.06
  Top 0.254: 34.29,4.06 31.24,4.06 30.23,3.05 28.45,3.05 J4.11
RB5
  Top 0.203: U1.20 39.87,10.41 34.04,4.57
  Top 0.254: 34.04,4.57 30.99,4.57 29.97,3.56 28.19,3.56 27.69,3.05 25.91,3.05 J4.10
RB8
  Top 0.203: U1.32 46.37,5.47 44.45,3.56
  Top 0.254: 44.45,3.56 39.12,3.56 J4.15
RB9
  Top 0.203: U1.33 46.77,5.11 44.7,3.05
  Top 0.254: 44.7,3.05 41.15,3.05 J4.16
RB10  (via drill 0.38)
  Top 0.203: U1.34 47.17,7.7 v46.48,8.38
  Bottom 0.254: J4.17 42.42,3.94 46.48,8 v46.48,8.38
RB11  (via drill 0.38)
  Top 0.203: U1.35 47.57,8.57 v46.48,9.65
  Bottom 0.254: v46.48,9.65 47.37,8.76 47.37,7.87 44.96,5.46 J4.18
RB12
  Top 0.203: U1.41 49.97,3.88 50.8,3.05
  Top 0.254: 50.8,3.05 53.21,3.05 54.48,1.78 J4.22
RB13  (via drill 0.38)
  Top 0.203: U1.42 50.37,8.18 v49.28,9.27
  Bottom 0.254: J4.23 57.15,1.78 50.04,8.89 49.66,9.27 v49.28,9.27
RB14
  Top 0.203: U1.43 50.77,3.84 51.05,3.56
  Top 0.254: 51.05,3.56 53.47,3.56 53.98,3.05 58.93,3.05 J4.24
RB15
  Top 0.203: U1.44 51.17,4.2 51.31,4.06
  Top 0.254: 51.31,4.06 53.72,4.06 54.23,3.56 60.96,3.56 J4.25
RC1  (via drill 0.38)
  Top 0.203: U1.6 40,16.01 38.73,17.27 v38.73,17.91
  Bottom 0.254: J3.38 6.86,22.86 9.27,20.45 11.05,20.45 19.3,20.45 19.81,19.94 36.7,19.94 v38.73,17.91
RC2  (via drill 0.38)
  Top 0.203: U1.7 39.64,15.61 37.59,17.65
  Top 0.254: v37.47,17.91 37.47,17.78 37.59,17.65
  Bottom 0.254: J3.39 9.02,19.94 19.05,19.94 19.56,19.43 35.94,19.43 v37.47,17.91
RC3  (via drill 0.38)
  Top 0.203: U1.8 38.89,15.21 v36.2,17.91
  Bottom 0.254: v36.2,17.91 35.18,18.92 19.3,18.92 18.8,19.43 6.99,19.43 J3.40
RC4  (via drill 0.38, 0.38 pad 0.25)
  Top 0.203: U1.9 39.83,14.81 v38.73,13.72
  Top 0.254: J4.1 4.32,4.32 4.32,9.14 v5.84,10.67
  Bottom 0.254: v38.73,13.72 36.07,11.05 13.08,11.05 12.32,11.81 6.99,11.81 v5.84,10.67
RC13  (via drill 0.38)
  Top 0.203: U1.73 54.55,17.21 53.85,16.51 53.85,16.26 52.45,14.86 51.82,14.86 v51.05,14.1 | C17.1 Q2.X1 67.69,20.83 68.07,20.45 v71.12,20.45
  Bottom 0.203: 59.82,19.68 58.93,18.8 56.52,18.8 52.58,14.86 51.82,14.86 v51.05,14.1 | 71.12,19.68 v71.12,20.45 | 75.56,19.68 J3.9
  Bottom 0.254: 59.82,19.68 71.12,19.68 75.56,19.68
RC14
  Top 0.203: 66.55,17.53 56.52,17.53 56.43,17.61 U1.74 | C16.1 Q2.X2 66.55,17.53 | 66.55,17.53 67.44,17.53
  Top 0.254: 67.44,17.53 69.34,19.43 71.5,19.43 74.17,22.1 75.44,22.1 J3.10
RD0
  Top 0.203: U1.72 56.56,16.81 56.81,17.06
  Top 0.254: 56.81,17.06 67.73,17.06 69.6,18.92 71.75,18.92 74.42,21.59 75.69,21.59 77.47,23.37 81.79,23.37 J3.8
RD1  (via drill 0.38)
  Top 0.203: v54.86,19.56 54.1,19.56 53.75,19.91 U1.76
  Bottom 0.203: J3.11 74.8,24.64 73.53,23.37 71.63,23.37 69.09,20.83 55.63,20.83 54.86,20.07 v54.86,19.56
RD2  (via drill 0.38)
  Top 0.203: U1.77 53.17,18.71 53.47,18.41 v53.59,18.41
  Bottom 0.203: J3.12 72.14,24.64 68.83,21.34 55.25,21.34 53.59,19.68 v53.59,18.41
RD3  (via drill 0.38)
  Top 0.203: U1.78 52.77,17.21 v51.69,16.13
  Bottom 0.203: v51.69,16.13 52.83,17.27 52.83,19.56 55.12,21.84 67.56,21.84 J3.13
RD4
  Top 0.203: U1.81 51.57,21.85 52.58,22.86
  Top 0.254: 52.58,22.86 58.55,22.86 59.05,23.37 60.83,23.37 62.1,24.64 J3.16
RD5
  Top 0.203: U1.82 51.17,22.21 52.32,23.37
  Top 0.254: 52.32,23.37 58.29,23.37 59.56,24.64 J3.17
RD6  (via drill 0.38)
  Top 0.203: v49.91,15.75 50.16,15.75 50.93,16.51 50.93,17.27 50.77,17.43 U1.83
  Bottom 0.203: v49.91,15.75 50.16,15.75 50.93,16.51 50.93,17.27 50.8,17.4 50.8,19.43 54.74,23.37 57.15,23.37 57.66,23.88
  Bottom 0.254: 57.66,23.88 J3.18
RD7  (via drill 0.38)
  Top 0.203: U1.84 50.37,17.07 50.19,16.89 v50.16,16.89
  Bottom 0.203: v50.16,16.89 50.16,19.56 55.12,24.51
  Bottom 0.254: 55.12,24.51 J3.19
RD8
  Top 0.203: U1.68 56.48,15.21 57.25,15.97
  Top 0.254: 57.25,15.97 68.17,15.97 70.1,17.91 72.26,17.91 74.93,20.57 76.2,20.57 77.98,22.35 90.93,22.35 J3.4
RD9  (via drill 0.38)
  Top 0.203: v53.72,14.22 53.72,14.86 54.47,15.61 U1.69
  Bottom 0.203: v53.72,14.22 53.72,14.73 56.97,17.98 59.64,17.98 60.33,18.67
  Bottom 0.254: 60.33,18.67 80.39,18.67 85.09,23.37 89.41,23.37 J3.5
RD10
  Top 0.203: U1.70 56.52,16.01 57.03,16.52
  Top 0.254: 57.03,16.52 67.95,16.52 69.85,18.41 72.01,18.41 74.68,21.08 75.95,21.08 77.72,22.86 86.36,22.86 J3.6
RD11  (via drill 0.38)
  Top 0.203: U1.71 54.51,16.41 54.36,16.26 54.36,16.13 v52.32,14.1
  Bottom 0.203: v52.32,14.1 52.45,14.1 56.74,18.39 59.28,18.39 60.07,19.18
  Bottom 0.254: 60.07,19.18 80.14,19.18 J3.7
RD12  (via drill 0.38)
  Top 0.203: U1.79 52.37,17.95 v51.69,17.27
  Bottom 0.203: v51.69,17.27 52.32,17.91 52.32,19.68 54.99,22.35 65.53,22.35 J3.14
RD13  (via drill 0.38)
  Top 0.203: U1.80 51.97,18.82 v51.56,18.41
  Bottom 0.203: v51.56,18.41 51.56,19.56 54.86,22.86 63.5,22.86 J3.15
RD14  (via drill 0.38)
  Top 0.203: v51.05,9.65 51.05,9.02 52.37,7.7 U1.47
  Bottom 0.254: J4.26 64.01,3.05 56.9,3.05 51.05,8.89 v51.05,9.65
RD15  (via drill 0.38)
  Top 0.203: U1.48 52.77,8.06 52.2,8.64 v52.2,9.14
  Bottom 0.254: v52.2,9.14 52.2,8.51 57.15,3.56 66.04,3.56 J4.27
RE0  (via drill 0.38)
  Top 0.203: U1.93 46.77,17.18 v46.61,17.02
  Top 0.254: v19.05,13.84 19.05,10.92 19.81,10.16 23.88,10.16 24.51,9.52 27.18,9.52 27.69,9.02 LED3.C
  Bottom 0.254: v19.05,13.84 19.05,15.24 20.57,16.76 33.78,16.76 35.05,15.49 45.34,15.49 46.61,16.76 v46.61,17.02 46.61,18.54 44.45,20.7 41.28,20.7 39.5,20.7 37.34,22.86 J3.26
RE1  (via drill 0.38)
  Top 0.203: U1.94 46.37,18.68 v45.72,18.03
  Top 0.254: v18.16,12.95 18.16,11.05 19.56,9.65 23.11,9.65 23.88,8.89 LED2.C
  Bottom 0.254: v18.16,12.95 18.16,15.24 20.19,17.27 34.04,17.27 35.31,16 44.96,16 45.72,16.76 v45.72,18.03 43.82,19.94 39.5,19.94 J3.27
RE2  (via drill 0.38)
  Top 0.203: 44.45,21.59 44.77,21.27 U1.98 44.77,17.08
  Top 0.254: 44.45,21.59 27.69,21.59 J3.31 | v44.83,17.14 44.77,17.08 | v17.27,13.84 17.27,10.92 19.3,8.89 20.19,8.89 20.18,8.88 LED1.C
  Bottom 0.254: v44.83,17.14 44.2,16.51 35.56,16.51 34.29,17.78 19.68,17.78 17.27,15.37 v17.27,13.84
RE3  (via drill 0.38)
  Top 0.203: 25.65,21.08 44.2,21.08 44.37,20.91 U1.99 44.37,18.46 v43.94,18.03
  Top 0.254: 25.65,21.08 J3.32 | v16.38,12.95 16.38,9.27 16.26,9.14 USB.C
  Bottom 0.254: v43.94,18.03 42.93,17.02 35.81,17.02 34.54,18.29 19.3,18.29 16.38,15.37 v16.38,12.95
RE4
  Top 0.203: U1.100 43.97,20.17 43.69,20.45 25.53,20.45
  Top 0.254: J3.33 20.83,23.37 22.61,23.37 25.53,20.45
RE5
  Top 0.203: U1.3 41.09,17.21 40.77,17.53 40.77,18.67
  Top 0.254: J3.35 15.75,23.37 20.07,23.37 20.57,22.86 22.35,22.86 25.27,19.94 39.5,19.94 40.77,18.67
RE6  (via drill 0.38)
  Top 0.203: U1.4 40.72,16.81 40.26,17.27 40.26,18.41
  Top 0.254: 24.26,20.19 22.1,22.35 20.32,22.35 19.81,22.86 13.72,22.86 J3.36 | 24.26,20.19 25.02,19.43 39.24,19.43 40.26,18.41 | 24.26,20.19 USER.3 USER.4 15.62,20.19 15.11,19.68 v15.11,17.53 | v14.22,14.86 14.21,14.86 R5.2
  Bottom 0.254: v15.11,17.53 15.11,15.75 v14.22,14.86
RE7  (via drill 0.38)
  Top 0.203: U1.5 40.36,16.41 39.75,17.02 39.75,18.16
  Top 0.254: 9.4,20.19 PROGRAM.4 8.13,23.37 J3.37 | 9.4,20.19 PROGRAM.3 | 39.75,18.16 38.99,18.92 17.02,18.92 v16.51,18.41 | v9.4,18.41 9.4,20.19 | R3.2 11.54,13.86 v11.94,13.46
  Bottom 0.254: v16.51,18.41 v9.4,18.41 9.4,18.29 11.94,15.75 v11.94,13.46
RE8
  Top 0.203: U1.18 39.15,11.21 33.53,5.59
  Top 0.254: 33.53,5.59 30.48,5.59 29.46,4.57 27.69,4.57 27.18,4.06 25.4,4.06 24.89,3.56 23.11,3.56 22.61,3.05 20.83,3.05 J4.8
RE9
  Top 0.203: U1.19 39.51,10.81 33.78,5.08
  Top 0.254: 33.78,5.08 30.73,5.08 29.72,4.06 27.94,4.06 27.43,3.56 25.65,3.56 25.15,3.05 23.37,3.05 J4.9
RF0  (via drill 0.38)
  Top 0.203: U1.87 49.17,18.94 v48.64,18.41
  Bottom 0.254: J3.20 51.94,24.64 50.67,23.37 49.28,23.37 48.64,22.73 v48.64,18.41
RF1
  Top 0.203: U1.88 48.77,23.37 J3.21
RF2  (via drill 0.38)
  Top 0.203: U1.52 56.47,8.81 56.77,8.51 56.77,7.87 v56.52,7.62
  Bottom 0.254: v56.52,7.62 57.4,6.73 59.82,6.73 61.98,4.57 72.64,4.57 J4.30
RF4  (via drill 0.38)
  Top 0.203: U1.49 53.17,7.45 53.34,7.62 54.36,7.62 v54.61,7.37
  Bottom 0.254: v54.61,7.37 57.91,4.06 68.07,4.06 J4.28
RF5
  Top 0.203: U1.50 53.85,6.22
  Top 0.254: J4.29 71.63,3.05 64.14,3.05 62.48,4.7 58.8,4.7 57.28,6.22 53.85,6.22
RF8  (via drill 0.38)
  Top 0.203: U1.53 56.83,9.21 57.79,8.25 v57.79,7.87
  Bottom 0.254: v57.79,7.87 58.42,7.24 60.07,7.24 62.23,5.08 74.93,5.08 77.98,2.03 J4.31
RF12  (via drill 0.38)
  Top 0.203: U1.40 49.57,7.71 v49.28,8
  Bottom 0.254: J4.21 52.58,5.08 49.66,8 v49.28,8
RF13
  Top 0.203: U1.39 49.17,5.57 49.4,5.33 49.4,2.41 J4.20
RG0
  Top 0.203: J3.23 45.59,24.64 46.86,23.37 47.12,23.37 47.97,22.52 U1.90
RG1
  Top 0.203: U1.89 48.37,23.77 J3.22
RG6  (via drill 0.38)
  Top 0.203: U1.10 46.54,14.41 v46.99,14.86
  Top 0.254: v5.59,8.89 5.59,3.05 J4.2
  Bottom 0.254: v5.59,8.89 8,11.3 12.07,11.3 12.83,10.54 37.08,10.54 41.02,14.48 46.61,14.48 v46.99,14.86
RG7  (via drill 0.38)
  Top 0.203: U1.11 47.97,14.01 v48.01,13.97
  Top 0.254: J4.3 v6.86,8.89
  Bottom 0.254: v6.86,8.89 8.76,10.8 11.81,10.8 12.57,10.03 37.34,10.03 41.28,13.97 v48.01,13.97
RG8  (via drill 0.38)
  Top 0.203: U1.12 46.59,13.61 v47.12,13.08
  Top 0.254: J4.4 9.65,2.03 9.65,7.49 v8.25,8.89
  Bottom 0.254: v8.25,8.89 9.65,10.29 11.56,10.29 12.32,9.52 37.59,9.52 41.53,13.46 46.74,13.46 v47.12,13.08
RG9  (via drill 0.38)
  Top 0.203: U1.14 44.85,12.81 v45.59,12.07
  Top 0.254: J4.6 10.92,5.33 v10.92,8.89
  Bottom 0.254: v10.92,8.89 11.3,8.51 38.1,8.51 41.91,12.32 45.34,12.32 v45.59,12.07
RG12
  Top 0.203: U1.96 45.57,22 44.96,22.61
  Top 0.254: 44.96,22.61 31.75,22.61 J3.29
RG13
  Top 0.203: U1.97 45.17,21.63 44.7,22.1
  Top 0.254: 44.7,22.1 29.72,22.1 J3.30
RG14
  Top 0.203: U1.95 45.97,22.36 45.21,23.11
  Top 0.254: 45.21,23.11 33.78,23.11 J3.28
RG15  (via drill 0.38)
  Top 0.203: v41.66,18.92 41.66,18.41 U1.1
  Bottom 0.254: J3.34 21.21,20.45 37.08,20.45 38.1,19.43 41.15,19.43 v41.66,18.92
USBID  (via drill 0.38)
  Top 0.203: 55.47,7.27 U1.51 54.51,8.41 54.36,8.25 53.47,8.25 53.09,8.64 53.09,9.78 52.83,10.03 52.07,10.03 51.56,10.54 v51.56,11.94 | 58.29,6.73 R9.1
  Top 0.254: 58.29,6.73 56.01,6.73 55.47,7.27 | J8.ID 102.07,7.66 100.2,9.52 v99.19,9.52
  Bottom 0.203: 66.67,17.02 66.12,17.58 57.2,17.58 54.74,15.11 54.74,13.46 54.1,12.83 51.82,12.83 51.56,12.57 v51.56,11.94
  Bottom 0.254: 66.67,17.02 82.55,17.02 83.95,18.41 91.82,18.41 J6.4 95.12,15.11 95.12,12.19 97.79,9.52 v99.19,9.52
VBUS  (via drill 0.38)
  Top 0.203: U1.54 54.44,9.61 v53.98,9.14
  Top 0.254: 88.27,14.48 88.14,14.48 88.17,14.45 PWR_SEL.6 88.27,14.48 | 88.27,14.48 88.22,14.52 | 88.27,14.48 88.27,14.35 | C3.1 99.31,5.84 | 88.39,14.22 88.77,14.22 v89.41,13.59
  Top 0.406: 88.22,14.52 PWR_SEL.3 | J8.VBUS 101.42,5.26 100.84,5.84 C3.1 99.33,4.81 v99.57,4.57 | PWR_SEL.6 88.32,14.35 88.39,14.35 88.39,14.22
  Bottom 0.254: v53.98,9.14 57.15,12.32 57.15,14.35 58.17,15.37 59.94,15.37 60.58,14.73 60.58,13.72 63.75,10.54 66.17,10.54 66.93,9.78 90.3,9.78
  Bottom 0.406: 99.57,5.84 96.77,5.84 J6.1 90.68,9.4 | J7.VBUS 107.24,16.21 108.33,15.11 108.33,10.03 104.14,5.84 99.57,5.84 | 99.57,5.84 v99.57,4.57 | 90.68,9.4 JP1.2 | v89.41,13.59 89.41,10.67 90.3,9.78 90.68,9.4
VIN_RAW  (via drill 0.38)
  Top 0.254: 79.45,12.65 U3.3 78.99,12.62 78.99,9.4 78.36,8.76 78.36,7.87 77.98,7.49 76.2,7.49 75.57,6.86 C1.A | C1.A arc90 C1.A
  Top 0.406: v87.63,12.45 87.61,12.42 87.61,11.78 D1.C | 79.45,12.65 v80.52,13.72
  Bottom 0.406: v87.63,12.45 81.79,12.45 v80.52,13.72
VPP  (via drill 0.38)
  Top 0.203: U1.13 45.72,13.21 46.86,12.07 v48.01,12.07
  Top 0.254: 9.65,10.03 RESET.4 8,10.03 8.13,10.16 R10.2 8.13,12.57 7.24,12.57 6.35,13.46 v6.35,17.53 | 9.65,10.03 RESET.3 | 9.65,10.03 v9.65,8.89 10.29,8.25 10.29,3.43 J4.5
  Bottom 0.254: v9.65,8.89 9.65,9.4 10.03,9.78 11.3,9.78 12.07,9.02 37.85,9.02 41.78,12.95 45.97,12.95 46.86,12.07 v48.01,12.07 | v6.35,17.53 J5.1

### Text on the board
Bottom: 4/1/2010
tPlace: v26 | C2 | C1 | E7 | E6 | E5 | G15 | E4 | E3 | E2 | G13 | G12 | G14 | E1 | E0 | A7 | A6 | G0 | G1 | F1 | F0 | D7 | D6 | D5 | D4 | D3 | D2 | D1 | C14 | C13 | D0 | D11 | D10 | D9 | D8 | 3.3V | 5V | GND | C3 | \D13 | D12 | VPP | - | 3.3V | MX460 | GND | + | GND | 32KHz | ID | EXT | USB | J1 | PROG | USER | J2 | PGD | J6 | D+ | PGC | PWR_SEL | D- | RESET | 8MHz | B2 | 3.3 | 5 | GND | Host | VBUS | B1 | USB | LED1 | LED2 | LED3 | PWR | JP1 | schmalzhaus.com/UBW32 | USB | B0 | A1 | 4 | A1 | 5 | G6 | G7 | G8 | VPP | G9 | A0 | E8 | E9 | B5 | B4 | B3 | A9 | A10 | B8 | B9 | B10 | B11 | F13 | F12 | B12 | B13 | B14 | B15 | D14 | D15 | F4 | F5 | F2 | F8 | A2 | A3 | A4 | A5 | A1 | 3.3V | 5V | GND | C4 | J8
bPlace: USB | ICSP | - | GND | + | ID | J1 | J6 | D+ | J7 | D- | WWW.SCHMALZHAUS.COM/UBW32 | 3.3 | 5 | GND | Host | VBUS | JP1
tValues: LM1117 | LM1117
